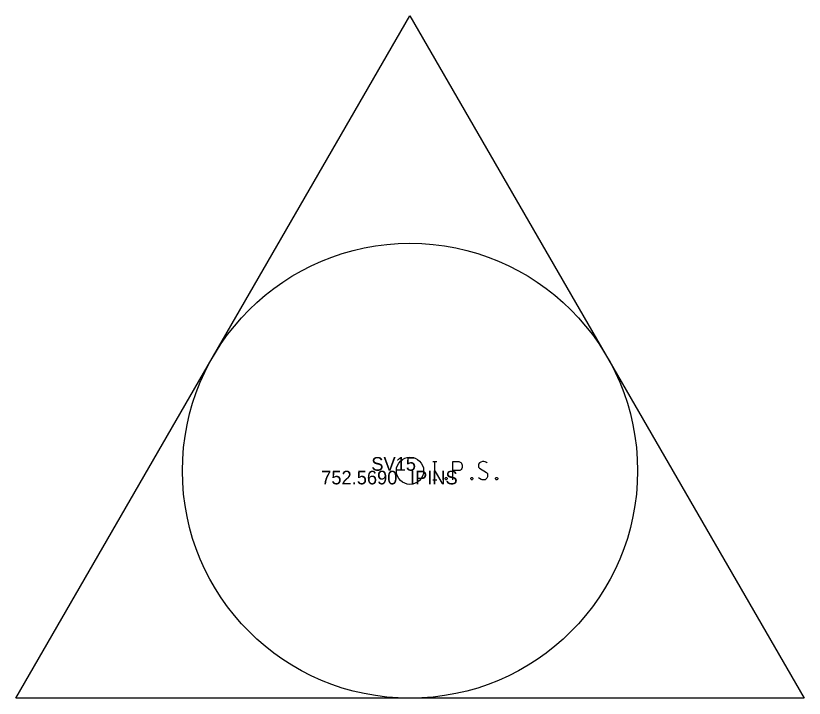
# Model space of a CAD drawing. Extents: x 1857339 to 1857830, y 693959 to 694359.
# Drawn here: x 1857339.056 to 1857342.52, y 693958.981 to 693961.981 of the extents above; entities that cross this region are included whole.
import ezdxf

# ---------------------------------------------------------------- set-up
doc = ezdxf.new("R2010")
doc.units = 0
for name, color, linetype in [('SV_Control_Point', 7, 'Continuous'), ('SV_P_Mon_Cells_Set', 7, 'Continuous'), ('SV_X_Text_Comment', 7, 'Continuous'), ('SV_X_Text_Elevation', 7, 'Continuous'), ('SV_X_Text_Name', 7, 'Continuous')]:
    doc.layers.add(name, color=color, linetype=linetype)

msp = doc.modelspace()

# ---------------------------------------------------------------- linework, layer by layer
at = {"layer": 'SV_Control_Point'}
for p, q in [((1857339.0555, 693958.9806), (1857340.7876, 693961.9806)), ((1857340.7876, 693961.9806), (1857342.5197, 693958.9806)), ((1857340.7876, 693959.9806), (1857340.7876, 693959.9806)), ((1857342.5197, 693958.9806), (1857339.0555, 693958.9806))]:
    msp.add_line(p, q, dxfattribs=at)
msp.add_circle((1857340.7876, 693959.9806), 1, dxfattribs=at)
at = {"layer": 'SV_P_Mon_Cells_Set'}
for points in [[(1857340.8885, 693960.0207), (1857340.9062, 693960.0207)], [(1857340.8974, 693959.9407), (1857340.8974, 693960.0207)], [(1857340.9756, 693959.9407), (1857340.9756, 693960.0207), (1857341.0021, 693960.0207), (1857341.0048, 693960.0201), (1857341.0087, 693960.0188), (1857341.0104, 693960.0175), (1857341.012, 693960.0163), (1857341.0142, 693960.0131), (1857341.0159, 693960.01), (1857341.017, 693960.0049), (1857341.017, 693959.9974), (1857341.0164, 693959.9949), (1857341.0153, 693959.9911), (1857341.0131, 693959.9867), (1857341.0109, 693959.9848), (1857341.0093, 693959.9835), (1857341.0065, 693959.9823), (1857341.0021, 693959.9816), (1857340.9756, 693959.9816)], [(1857341.1261, 693960.015), (1857341.125, 693960.0163), (1857341.1233, 693960.0175), (1857341.1184, 693960.0194), (1857341.1123, 693960.0207), (1857341.1079, 693960.0207), (1857341.1063, 693960.0207), (1857341.0991, 693960.0188), (1857341.093, 693960.015), (1857341.0892, 693960.01), (1857341.0881, 693960.0049), (1857341.0881, 693960.0012), (1857341.0892, 693959.9961), (1857341.0936, 693959.9917), (1857341.1239, 693959.9728), (1857341.1266, 693959.9703), (1857341.1277, 693959.9678), (1857341.1288, 693959.964), (1857341.1288, 693959.9602), (1857341.1283, 693959.9564), (1857341.1277, 693959.9539), (1857341.1266, 693959.9508), (1857341.1255, 693959.9483), (1857341.1244, 693959.9464), (1857341.1228, 693959.9445), (1857341.1211, 693959.9432), (1857341.1189, 693959.942), (1857341.1173, 693959.9413), (1857341.1123, 693959.9407), (1857341.1046, 693959.9407), (1857341.0996, 693959.942), (1857341.0925, 693959.9464), (1857341.0881, 693959.9501)], [(1857340.9453, 693959.9514), (1857340.9481, 693959.9514), (1857340.9497, 693959.9501), (1857340.9514, 693959.9476), (1857340.9514, 693959.9445), (1857340.9497, 693959.942), (1857340.9481, 693959.9407), (1857340.9453, 693959.9407), (1857340.9437, 693959.942), (1857340.942, 693959.9445), (1857340.942, 693959.9476), (1857340.9437, 693959.9501), (1857340.9453, 693959.9514)], [(1857341.0578, 693959.9514), (1857341.0605, 693959.9514), (1857341.0622, 693959.9501), (1857341.0638, 693959.9476), (1857341.0638, 693959.9445), (1857341.0622, 693959.942), (1857341.0605, 693959.9407), (1857341.0578, 693959.9407), (1857341.0561, 693959.942), (1857341.0544, 693959.9445), (1857341.0544, 693959.9476), (1857341.0561, 693959.9501), (1857341.0578, 693959.9514)], [(1857341.1669, 693959.9514), (1857341.1696, 693959.9514), (1857341.1713, 693959.9501), (1857341.1729, 693959.9476), (1857341.1729, 693959.9445), (1857341.1713, 693959.942), (1857341.1696, 693959.9407), (1857341.1669, 693959.9407), (1857341.1652, 693959.942), (1857341.1636, 693959.9445), (1857341.1636, 693959.9476), (1857341.1652, 693959.9501), (1857341.1669, 693959.9514)], [(1857340.8885, 693959.9407), (1857340.9062, 693959.9407)]]:
    msp.add_lwpolyline(points, dxfattribs=at)
msp.add_circle((1857340.7876, 693959.9806), 0.06, dxfattribs=at)

# ---------------------------------------------------------------- texts
at = {"layer": 'SV_X_Text_Comment'}
msp.add_text('IPINS', height=0.06, dxfattribs=at).set_placement((1857340.7876, 693959.9206))
at = {"layer": 'SV_X_Text_Elevation'}
msp.add_text('752.5690', height=0.06, dxfattribs=at).set_placement((1857340.3974, 693959.9206))
at = {"layer": 'SV_X_Text_Name'}
msp.add_text('SV15', height=0.06, dxfattribs=at).set_placement((1857340.6176, 693959.9806))

doc.saveas('drawing.dxf')
